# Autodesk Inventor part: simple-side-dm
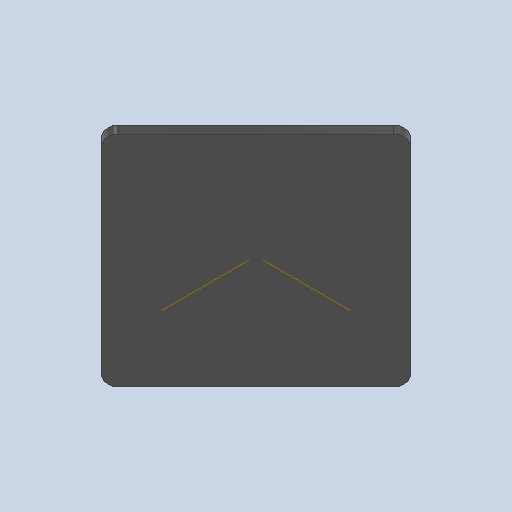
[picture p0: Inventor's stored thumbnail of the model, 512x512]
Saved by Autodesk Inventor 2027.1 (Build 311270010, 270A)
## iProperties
Created: 2026-07
Part Number: simple-side-dm
Material: Generic
Document SubType Name: Modeling
Designer: dunge
Density: 1 g/cm^3
Appearance: Default
Author: dunge
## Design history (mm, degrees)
sketch "Sketch1"
  geometry: L1 (0.508, -0.508)-(-0.508, 0.508); L2 (-0.508, 0.508)-(-10.668, -9.652); L3 (-10.668, -9.652)-(-9.652, -10.668); L4 (-9.652, -10.668)-(0.508, -0.508); L5 (0, 0)-(0.419, 0)
  constraints: 10 end point, 3 perpendicular, 2 midpoint, 1 horizontal
  dimensions: "d0" = 45 deg angle of L1 L5; "d1" = 1.016 horizontal distance of L1.start L1.end; "d2" = 10.16 horizontal distance of L3.end L1.start
revolve "Revolution1" sketch "Sketch1" stored, may be unused: angle "d3" = 90 deg
workpoint "Work Point1"
  workaxis "Work Axis3"
  workaxis "Work Axis4"
sketch "Sketch2"
  geometry: L1 (-14.368, -14.368)-(14.368, -14.368); L2 (14.368, -14.368)-(14.368, 14.368); L3 (14.368, 14.368)-(-14.368, 14.368); L4 (-14.368, 14.368)-(-14.368, -14.368); L5 (-14.368, -14.368)-(14.368, 14.368); L6 (14.368, -14.368)-(-14.368, 14.368); C1 r 14.368 at (0, 0) reference; 5 further points
  constraints: 12 end point, 2 midpoint, 2 parallel, 2 tangent, 1 horizontal, 1 perpendicular
extrude "Extrusion1" join sketch "Sketch2" stored distance "d4" = 25.4; taper "d5" = 0 deg
fillet "Fillet1" dims "d6" = 1.5875
body "Solid1"
node "Finishes"
node "Finish1" dims "Finish1_Area" = 164.7283
node "Finish2" dims "Finish2_Area" = 98.48864
